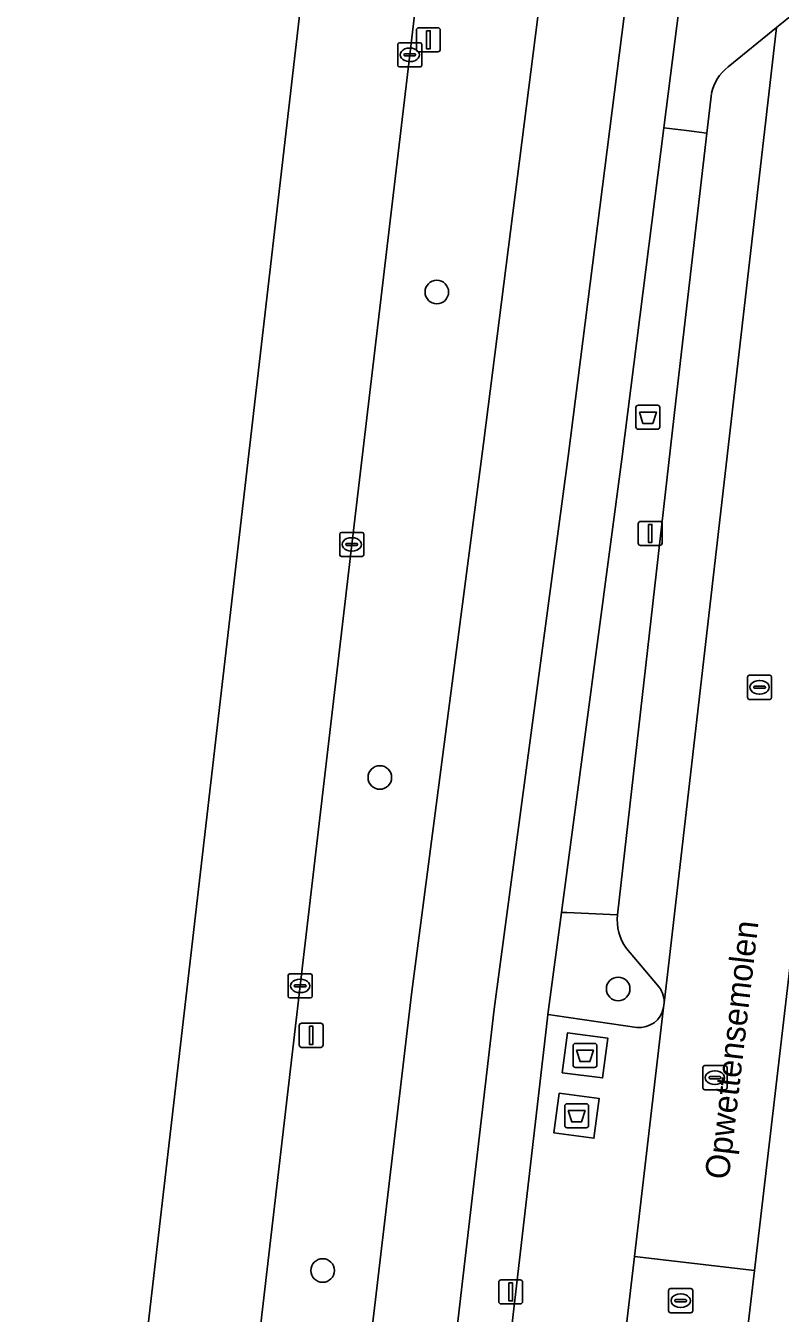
# Model space of a CAD drawing. Extents: x 161241 to 161758, y 384138 to 384885.
# Drawn here: x 161277.3 to 161308.6, y 384518.6 to 384572 of the extents above; entities that cross this region are included whole.
import ezdxf

# ---------------------------------------------------------------- set-up
doc = ezdxf.new("R2010")
doc.units = 0
for name, color, linetype in [('IMGEO_Afval_apart_plaats', 7, 'Continuous'), ('IMGEO_Afvalbak', 7, 'Continuous'), ('IMGEO_Berm_groen', 7, 'Continuous'), ('IMGEO_Boom', 7, 'Continuous'), ('IMGEO_Fietspad_gesloten', 7, 'Continuous'), ('IMGEO_Kolk', 7, 'Continuous'), ('IMGEO_Lichtmast', 7, 'Continuous'), ('IMGEO_Openbare_ruimte_label', 7, 'Continuous'), ('IMGEO_OVBaan_gesloten', 7, 'Continuous'), ('IMGEO_Parkeervlak_open', 7, 'Continuous'), ('IMGEO_Rijbaan_lokaal_open', 7, 'Continuous'), ('IMGEO_Rioolput', 7, 'Continuous'), ('IMGEO_Voetpad_gesloten', 7, 'Continuous'), ('IMGEO_Voetpad_open', 7, 'Continuous')]:
    doc.layers.add(name, color=color, linetype=linetype)

msp = doc.modelspace()

# ---------------------------------------------------------------- linework, layer by layer
at = {"layer": 'IMGEO_Afval_apart_plaats'}
for p, q in [((161300.028, 384528.867), (161300.028, 384529.667)), ((161300.028, 384529.667), (161300.028, 384528.867)), ((161300.128, 384529.767), (161300.918, 384529.767)), ((161300.918, 384529.767), (161300.128, 384529.767)), ((161301.018, 384529.667), (161301.018, 384528.867)), ((161301.018, 384528.867), (161301.018, 384529.667)), ((161300.918, 384528.767), (161300.128, 384528.767)), ((161300.128, 384528.767), (161300.918, 384528.767)), ((161299.68, 384526.363), (161299.68, 384527.163)), ((161299.68, 384527.163), (161299.68, 384526.363)), ((161299.78, 384527.263), (161300.57, 384527.263)), ((161300.57, 384527.263), (161299.78, 384527.263)), ((161300.67, 384527.163), (161300.67, 384526.363)), ((161300.67, 384526.363), (161300.67, 384527.163)), ((161300.57, 384526.263), (161299.78, 384526.263)), ((161299.78, 384526.263), (161300.57, 384526.263))]:
    msp.add_line(p, q, dxfattribs=at)
for points in [[(161300.171, 384529.481), (161300.875, 384529.481), (161300.726, 384529.011), (161300.32, 384529.011), (161300.171, 384529.481)], [(161299.823, 384526.977), (161300.527, 384526.977), (161300.378, 384526.507), (161299.972, 384526.507), (161299.823, 384526.977)]]:
    msp.add_lwpolyline(points, dxfattribs=at)
for centre, start, end in [((161300.128, 384529.667), 90, 180), ((161300.128, 384529.667), 90, 180), ((161300.918, 384529.667), 0, 90), ((161300.918, 384529.667), 360, 90), ((161300.128, 384528.867), 180, 270), ((161300.128, 384528.867), 180, 270), ((161300.918, 384528.867), 270, 0), ((161300.918, 384528.867), 270, 0), ((161299.78, 384527.163), 90, 180), ((161299.78, 384527.163), 90, 180), ((161300.57, 384527.163), 0, 90), ((161300.57, 384527.163), 360, 90), ((161299.78, 384526.363), 180, 270), ((161299.78, 384526.363), 180, 270), ((161300.57, 384526.363), 270, 0), ((161300.57, 384526.363), 270, 0)]:
    msp.add_arc(centre, 0.1, start, end, dxfattribs=at)
at = {"layer": 'IMGEO_Afvalbak'}
for p, q in [((161302.637, 384555.341), (161302.637, 384556.141)), ((161302.637, 384556.141), (161302.637, 384555.341)), ((161302.737, 384556.241), (161303.527, 384556.241)), ((161303.527, 384556.241), (161302.737, 384556.241)), ((161303.627, 384556.141), (161303.627, 384555.341)), ((161303.627, 384555.341), (161303.627, 384556.141)), ((161303.527, 384555.241), (161302.737, 384555.241)), ((161302.737, 384555.241), (161303.527, 384555.241))]:
    msp.add_line(p, q, dxfattribs=at)
msp.add_lwpolyline([(161302.78, 384555.955), (161303.484, 384555.955), (161303.335, 384555.485), (161302.929, 384555.485), (161302.78, 384555.955)], dxfattribs=at)
for centre, start, end in [((161302.737, 384556.141), 90, 180), ((161302.737, 384556.141), 90, 180), ((161303.527, 384556.141), 0, 90), ((161303.527, 384556.141), 360, 90), ((161302.737, 384555.341), 180, 270), ((161302.737, 384555.341), 180, 270), ((161303.527, 384555.341), 270, 0), ((161303.527, 384555.341), 270, 0)]:
    msp.add_arc(centre, 0.1, start, end, dxfattribs=at)
at = {"layer": 'IMGEO_Berm_groen'}
for points in [[(161278.307, 384403.15), (161286.202, 384471.417), (161293.323, 384531.813), (161296.311, 384554.647), (161300.999, 384591.473), (161306.453, 384637.728), (161301.117, 384638.364), (161300.355, 384631.67), (161297.994, 384611.38), (161295.634, 384591.049), (161293.255, 384570.775), (161290.848, 384550.464), (161288.707, 384532.15), (161288.472, 384530.133), (161286.341, 384511.851), (161283.768, 384490.025), (161281.583, 384471.698), (161279.185, 384451.364)], [(161306.46, 384570.27), (161308.464, 384571.907), (161309.261, 384572.542), (161308.413, 384573.592), (161305.263, 384577.494), (161305.062, 384577.742), (161303.794, 384567.742), (161304.73, 384567.63), (161305.574, 384567.529), (161305.764, 384569.177)], [(161301.866, 384535.1), (161299.776, 384535.191), (161299.549, 384535.196), (161298.986, 384530.962), (161299.086, 384530.946), (161299.265, 384530.92), (161302.672, 384530.431)], [(161303.525, 384532.183), (161302.238, 384533.704)], [(161303.783, 384531.252), (161303.807, 384531.45)]]:
    msp.add_lwpolyline(points, dxfattribs=at)
msp.add_lwpolyline([(161305.574, 384567.529), (161304.73, 384567.63), (161303.794, 384567.742), (161302.052, 384554.002), (161299.549, 384535.196), (161299.776, 384535.191), (161301.866, 384535.1), (161304.293, 384556.423)], close=True, dxfattribs=at)
for centre, radius, start, end in [((161307.568, 384568.797), 1.843, 126.9338, 168.0899), ((161304.006, 384534.923), 2.147, 175.2616, 214.5808), ((161302.796, 384531.482), 1.012, 358.2094, 43.8761), ((161302.782, 384531.445), 1.02, 263.834, 349.0929)]:
    msp.add_arc(centre, radius, start, end, dxfattribs=at)
at = {"layer": 'IMGEO_Boom'}
for centre in [(161294.375, 384560.934), (161292.011, 384540.797), (161301.899, 384532.026), (161289.64, 384520.345)]:
    msp.add_circle(centre, 0.489, dxfattribs=at)
at = {"layer": 'IMGEO_Fietspad_gesloten'}
for points in [[(161258.742, 384157.135), (161260.876, 384184.71), (161262.854, 384210.484), (161266.448, 384261.586), (161267.146, 384270.325), (161268.291, 384284.663), (161268.569, 384287.683), (161268.583, 384287.814), (161270.005, 384301.578), (161270.134, 384303.063), (161273.019, 384327.449), (161276.269, 384355.259), (161281.811, 384402.692), (161289.671, 384470.352), (161296.755, 384531.182), (161299.82, 384554.106), (161304.483, 384590.763), (161310.58, 384642.356), (161311.044, 384646.284), (161311.712, 384651.942), (161311.774, 384652.424)], [(161308.263, 384652.525), (161306.453, 384637.728), (161300.999, 384591.473), (161296.311, 384554.647), (161293.323, 384531.813), (161286.202, 384471.417), (161278.307, 384403.15), (161275.866, 384382.258), (161272.845, 384356.399), (161269.542, 384328.133), (161269.524, 384327.978), (161266.559, 384302.554), (161265.412, 384302.67), (161262.065, 384303.024), (161261.777, 384300.445), (161262.272, 384300.399), (161264.329, 384300.231)]]:
    msp.add_lwpolyline(points, dxfattribs=at)
at = {"layer": 'IMGEO_Kolk'}
for p, q in [((161292.829, 384571.275), (161293.681, 384571.275)), ((161292.754, 384570.349), (161292.754, 384571.201)), ((161293.013, 384570.769), (161293.013, 384570.781)), ((161293.451, 384570.732), (161293.053, 384570.732)), ((161293.056, 384570.818), (161293.454, 384570.818)), ((161293.242, 384571.055), (161293.267, 384571.055)), ((161293.497, 384570.781), (161293.497, 384570.769)), ((161293.755, 384571.201), (161293.755, 384570.349)), ((161293.681, 384570.275), (161292.829, 384570.275)), ((161293.265, 384570.495), (161293.24, 384570.495)), ((161290.422, 384550.964), (161291.274, 384550.964)), ((161290.347, 384550.038), (161290.347, 384550.89)), ((161290.606, 384550.458), (161290.606, 384550.47)), ((161291.044, 384550.421), (161290.646, 384550.421)), ((161290.649, 384550.507), (161291.047, 384550.507)), ((161290.835, 384550.744), (161290.86, 384550.744)), ((161291.09, 384550.47), (161291.09, 384550.458)), ((161291.348, 384550.89), (161291.348, 384550.038)), ((161291.274, 384549.964), (161290.422, 384549.964)), ((161290.858, 384550.184), (161290.833, 384550.184)), ((161307.34, 384545.038), (161308.192, 384545.038)), ((161307.265, 384544.112), (161307.265, 384544.964)), ((161307.524, 384544.532), (161307.524, 384544.544)), ((161307.567, 384544.581), (161307.965, 384544.581)), ((161307.753, 384544.818), (161307.778, 384544.818)), ((161308.008, 384544.544), (161308.008, 384544.532)), ((161308.266, 384544.964), (161308.266, 384544.112)), ((161308.192, 384544.038), (161307.34, 384544.038)), ((161307.962, 384544.495), (161307.564, 384544.495)), ((161307.776, 384544.258), (161307.751, 384544.258)), ((161288.206, 384531.724), (161288.206, 384532.576)), ((161288.281, 384532.65), (161289.133, 384532.65)), ((161288.694, 384532.43), (161288.719, 384532.43)), ((161289.207, 384532.576), (161289.207, 384531.724)), ((161288.465, 384532.144), (161288.465, 384532.156)), ((161288.903, 384532.107), (161288.505, 384532.107)), ((161288.508, 384532.193), (161288.906, 384532.193)), ((161288.717, 384531.87), (161288.692, 384531.87)), ((161288.949, 384532.156), (161288.949, 384532.144)), ((161289.133, 384531.65), (161288.281, 384531.65)), ((161305.413, 384527.916), (161305.413, 384528.768)), ((161305.488, 384528.842), (161306.34, 384528.842)), ((161305.901, 384528.622), (161305.926, 384528.622)), ((161306.414, 384528.768), (161306.414, 384527.916)), ((161305.672, 384528.336), (161305.672, 384528.348)), ((161306.11, 384528.299), (161305.712, 384528.299)), ((161305.715, 384528.385), (161306.113, 384528.385)), ((161305.924, 384528.062), (161305.899, 384528.062)), ((161306.156, 384528.348), (161306.156, 384528.336)), ((161306.34, 384527.842), (161305.488, 384527.842))]:
    msp.add_line(p, q, dxfattribs=at)
for points in [[(161292.829, 384571.275), (161293.681, 384571.275)], [(161292.754, 384570.349), (161292.754, 384571.201)], [(161293.755, 384571.201), (161293.755, 384570.349)], [(161293.681, 384570.275), (161292.829, 384570.275)], [(161290.422, 384550.964), (161291.274, 384550.964)], [(161290.347, 384550.038), (161290.347, 384550.89)], [(161291.348, 384550.89), (161291.348, 384550.038)], [(161291.274, 384549.964), (161290.422, 384549.964)], [(161307.34, 384545.038), (161308.192, 384545.038)], [(161307.265, 384544.112), (161307.265, 384544.964)], [(161308.266, 384544.964), (161308.266, 384544.112)], [(161308.192, 384544.038), (161307.34, 384544.038)], [(161288.206, 384531.724), (161288.206, 384532.576)], [(161288.281, 384532.65), (161289.133, 384532.65)], [(161289.207, 384532.576), (161289.207, 384531.724)], [(161289.133, 384531.65), (161288.281, 384531.65)], [(161305.413, 384527.916), (161305.413, 384528.768)], [(161305.488, 384528.842), (161306.34, 384528.842)], [(161306.414, 384528.768), (161306.414, 384527.916)], [(161306.34, 384527.842), (161305.488, 384527.842)]]:
    msp.add_lwpolyline(points, dxfattribs=at)
for centre, radius, start, end in [((161292.831, 384571.199), 0.0765, 91.552, 178.448), ((161292.831, 384571.199), 0.0765, 91.552, 178.448), ((161293.679, 384571.199), 0.0765, 1.552, 88.448), ((161293.679, 384571.199), 0.0765, 1.552, 88.448), ((161293.053, 384570.778), 0.0403, 85.8775, 175.7526), ((161293.05, 384570.768), 0.0366, 178.938, 274.7102), ((161293.454, 384570.775), 0.043, 264.8664, 352.4533), ((161293.458, 384570.78), 0.0386, 1.7309, 96.639), ((161292.831, 384570.351), 0.0765, 181.552, 268.448), ((161292.831, 384570.351), 0.0765, 181.552, 268.448), ((161293.679, 384570.351), 0.0765, 271.552, 358.448), ((161293.679, 384570.351), 0.0765, 271.552, 358.448), ((161290.424, 384550.888), 0.0765, 91.552, 178.448), ((161290.424, 384550.888), 0.0765, 91.552, 178.448), ((161291.272, 384550.888), 0.0765, 1.552, 88.448), ((161291.272, 384550.888), 0.0765, 1.552, 88.448), ((161290.646, 384550.467), 0.0403, 85.8775, 175.7526), ((161290.643, 384550.457), 0.0366, 178.938, 274.7102), ((161291.047, 384550.464), 0.043, 264.8664, 352.4533), ((161291.051, 384550.469), 0.0386, 1.7309, 96.639), ((161290.424, 384550.04), 0.0765, 181.552, 268.448), ((161290.424, 384550.04), 0.0765, 181.552, 268.448), ((161291.272, 384550.04), 0.0765, 271.552, 358.448), ((161291.272, 384550.04), 0.0765, 271.552, 358.448), ((161307.342, 384544.962), 0.0765, 91.552, 178.448), ((161307.342, 384544.962), 0.0765, 91.552, 178.448), ((161308.19, 384544.962), 0.0765, 1.552, 88.448), ((161308.19, 384544.962), 0.0765, 1.552, 88.448), ((161307.564, 384544.541), 0.0403, 85.8775, 175.7526), ((161307.561, 384544.531), 0.0366, 178.938, 274.7102), ((161307.965, 384544.538), 0.043, 264.8664, 352.4533), ((161307.969, 384544.543), 0.0386, 1.7309, 96.639), ((161307.342, 384544.114), 0.0765, 181.552, 268.448), ((161307.342, 384544.114), 0.0765, 181.552, 268.448), ((161308.19, 384544.114), 0.0765, 271.552, 358.448), ((161308.19, 384544.114), 0.0765, 271.552, 358.448), ((161288.283, 384532.574), 0.0765, 91.552, 178.448), ((161288.283, 384532.574), 0.0765, 91.552, 178.448), ((161289.131, 384532.574), 0.0765, 1.552, 88.448), ((161289.131, 384532.574), 0.0765, 1.552, 88.448), ((161288.283, 384531.726), 0.0765, 181.552, 268.448), ((161288.283, 384531.726), 0.0765, 181.552, 268.448), ((161288.505, 384532.153), 0.0403, 85.8775, 175.7526), ((161288.502, 384532.143), 0.0366, 178.938, 274.7102), ((161288.906, 384532.15), 0.043, 264.8664, 352.4533), ((161288.91, 384532.155), 0.0386, 1.7309, 96.639), ((161289.131, 384531.726), 0.0765, 271.552, 358.448), ((161289.131, 384531.726), 0.0765, 271.552, 358.448), ((161305.49, 384528.766), 0.0765, 91.552, 178.448), ((161305.49, 384528.766), 0.0765, 91.552, 178.448), ((161306.338, 384528.766), 0.0765, 1.552, 88.448), ((161306.338, 384528.766), 0.0765, 1.552, 88.448), ((161305.712, 384528.345), 0.0403, 85.8775, 175.7526), ((161305.709, 384528.335), 0.0366, 178.938, 274.7102), ((161306.113, 384528.342), 0.043, 264.8664, 352.4533), ((161306.117, 384528.347), 0.0386, 1.7309, 96.639), ((161305.49, 384527.918), 0.0765, 181.552, 268.448), ((161305.49, 384527.918), 0.0765, 181.552, 268.448), ((161306.338, 384527.918), 0.0765, 271.552, 358.448), ((161306.338, 384527.918), 0.0765, 271.552, 358.448)]:
    msp.add_arc(centre, radius, start, end, dxfattribs=at)
for centre, major_axis, ratio, start_param, end_param in [((161293.241, 384570.775), (-0.387, 0.002), 0.722429, 4.712389, 7.853982), ((161293.266, 384570.775), (-0.39, 0.002), 0.717154, 1.570796, 4.712389), ((161290.834, 384550.464), (-0.387, 0.002), 0.722429, 4.712389, 7.853982), ((161290.859, 384550.464), (-0.39, 0.002), 0.717154, 1.570796, 4.712389), ((161307.752, 384544.538), (-0.387, 0.002), 0.722429, 4.712389, 7.853982), ((161307.777, 384544.538), (-0.39, 0.002), 0.717154, 1.570796, 4.712389), ((161288.693, 384532.15), (-0.387, 0.002), 0.722429, 4.712389, 7.853982), ((161288.718, 384532.15), (-0.39, 0.002), 0.717154, 1.570796, 4.712389), ((161305.9, 384528.342), (-0.387, 0.002), 0.722429, 4.712389, 7.853982), ((161305.925, 384528.342), (-0.39, 0.002), 0.717154, 1.570796, 4.712389)]:
    msp.add_ellipse(centre, major_axis=major_axis, ratio=ratio, start_param=start_param, end_param=end_param, dxfattribs=at)
at = {"layer": 'IMGEO_Lichtmast'}
for p, q in [((161293.53, 384571.001), (161293.53, 384571.801)), ((161293.53, 384571.801), (161293.53, 384571.001)), ((161293.63, 384571.901), (161294.42, 384571.901)), ((161294.42, 384571.901), (161293.63, 384571.901)), ((161294.52, 384571.801), (161294.52, 384571.001)), ((161294.52, 384571.001), (161294.52, 384571.801)), ((161294.42, 384570.901), (161293.63, 384570.901)), ((161293.63, 384570.901), (161294.42, 384570.901)), ((161302.731, 384550.52), (161302.731, 384551.32)), ((161302.731, 384551.32), (161302.731, 384550.52)), ((161302.831, 384551.42), (161303.621, 384551.42)), ((161303.621, 384551.42), (161302.831, 384551.42)), ((161303.721, 384551.32), (161303.721, 384550.52)), ((161303.721, 384550.52), (161303.721, 384551.32)), ((161303.621, 384550.42), (161302.831, 384550.42)), ((161302.831, 384550.42), (161303.621, 384550.42)), ((161288.669, 384529.701), (161288.669, 384530.501)), ((161288.669, 384530.501), (161288.669, 384529.701)), ((161288.769, 384530.601), (161289.559, 384530.601)), ((161289.559, 384530.601), (161288.769, 384530.601)), ((161289.659, 384530.501), (161289.659, 384529.701)), ((161289.659, 384529.701), (161289.659, 384530.501)), ((161289.559, 384529.601), (161288.769, 384529.601)), ((161288.769, 384529.601), (161289.559, 384529.601)), ((161297.046, 384519.957), (161297.836, 384519.957)), ((161297.836, 384519.957), (161297.046, 384519.957)), ((161296.946, 384519.057), (161296.946, 384519.857)), ((161296.946, 384519.857), (161296.946, 384519.057)), ((161297.936, 384519.857), (161297.936, 384519.057)), ((161297.936, 384519.057), (161297.936, 384519.857)), ((161297.836, 384518.957), (161297.046, 384518.957)), ((161297.046, 384518.957), (161297.836, 384518.957))]:
    msp.add_line(p, q, dxfattribs=at)
for points in [[(161293.95, 384571.776), (161294.1, 384571.776), (161294.1, 384571.026), (161293.95, 384571.026), (161293.95, 384571.776)], [(161303.151, 384551.295), (161303.301, 384551.295), (161303.301, 384550.545), (161303.151, 384550.545), (161303.151, 384551.295)], [(161289.089, 384530.476), (161289.239, 384530.476), (161289.239, 384529.726), (161289.089, 384529.726), (161289.089, 384530.476)], [(161297.366, 384519.832), (161297.516, 384519.832), (161297.516, 384519.082), (161297.366, 384519.082), (161297.366, 384519.832)]]:
    msp.add_lwpolyline(points, dxfattribs=at)
for centre, start, end in [((161293.63, 384571.801), 90, 180), ((161293.63, 384571.801), 90, 180), ((161294.42, 384571.801), 0, 90), ((161294.42, 384571.801), 360, 90), ((161293.63, 384571.001), 180, 270), ((161293.63, 384571.001), 180, 270), ((161294.42, 384571.001), 270, 0), ((161294.42, 384571.001), 270, 0), ((161302.831, 384551.32), 90, 180), ((161302.831, 384551.32), 90, 180), ((161303.621, 384551.32), 0, 90), ((161303.621, 384551.32), 360, 90), ((161302.831, 384550.52), 180, 270), ((161302.831, 384550.52), 180, 270), ((161303.621, 384550.52), 270, 0), ((161303.621, 384550.52), 270, 0), ((161288.769, 384530.501), 90, 180), ((161288.769, 384530.501), 90, 180), ((161289.559, 384530.501), 0, 90), ((161289.559, 384530.501), 360, 90), ((161288.769, 384529.701), 180, 270), ((161288.769, 384529.701), 180, 270), ((161289.559, 384529.701), 270, 0), ((161289.559, 384529.701), 270, 0), ((161297.046, 384519.857), 90, 180), ((161297.046, 384519.857), 90, 180), ((161297.836, 384519.857), 0, 90), ((161297.836, 384519.857), 360, 90), ((161297.046, 384519.057), 180, 270), ((161297.046, 384519.057), 180, 270), ((161297.836, 384519.057), 270, 0), ((161297.836, 384519.057), 270, 0)]:
    msp.add_arc(centre, 0.1, start, end, dxfattribs=at)
at = {"layer": 'IMGEO_OVBaan_gesloten'}
for points in [[(161312.353, 384812.006), (161309.921, 384834.117), (161309.774, 384835.487), (161309.446, 384838.541), (161309.033, 384842.394), (161308.618, 384846.264), (161308.42, 384848.049), (161305.427, 384848.093), (161310.221, 384805.365), (161309.046, 384772.256), (161307.924, 384740.658), (161299.466, 384666.717), (161288.788, 384573.374), (161256.675, 384295.749), (161254.709, 384278.75), (161244.663, 384173.474), (161243.814, 384162.675), (161243.598, 384159.911), (161243.455, 384158.862), (161242.942, 384154.711), (161242.923, 384154.593), (161242.753, 384153.458), (161241.269, 384137.91)], [(161261.738, 384300.096), (161261.777, 384300.445), (161262.065, 384303.024), (161262.902, 384310.522), (161264.916, 384328.431), (161267.197, 384347.869), (161269.457, 384367.164), (161271.789, 384387.356), (161274.112, 384407.478), (161276.721, 384430.069), (161279.185, 384451.364), (161281.583, 384471.698), (161283.768, 384490.025), (161286.341, 384511.851), (161288.472, 384530.133), (161288.707, 384532.15), (161290.848, 384550.464), (161293.255, 384570.775), (161295.634, 384591.049), (161297.994, 384611.38), (161300.355, 384631.67), (161301.117, 384638.364), (161302.766, 384651.987), (161302.856, 384653.145)]]:
    msp.add_lwpolyline(points, dxfattribs=at)
at = {"layer": 'IMGEO_Parkeervlak_open'}
for points in [[(161303.807, 384531.45), (161303.973, 384532.865), (161308.464, 384571.907), (161306.46, 384570.27)], [(161305.764, 384569.177), (161305.574, 384567.529), (161304.293, 384556.423), (161301.866, 384535.1)], [(161302.238, 384533.704), (161303.525, 384532.183)], [(161300.111, 384500), (161302.017, 384516.22), (161302.57, 384520.925), (161303.783, 384531.252)], [(161302.672, 384530.431), (161299.265, 384530.92), (161299.086, 384530.946), (161298.986, 384530.962), (161298.968, 384530.827), (161291.483, 384466.168), (161291.644, 384466.15), (161295.04, 384465.761), (161296.054, 384465.353), (161299.421, 384494.132), (161300.111, 384500)]]:
    msp.add_lwpolyline(points, dxfattribs=at)
for points in [[(161299.582, 384528.546), (161299.793, 384530.202), (161301.465, 384529.988), (161301.254, 384528.333)], [(161299.236, 384526.051), (161299.458, 384527.698), (161301.113, 384527.474), (161300.891, 384525.828)]]:
    msp.add_lwpolyline(points, close=True, dxfattribs=at)
for centre, radius, start, end in [((161307.568, 384568.797), 1.843, 126.9338, 168.0899), ((161304.006, 384534.923), 2.147, 175.2616, 214.5808), ((161302.796, 384531.482), 1.012, 358.2094, 43.8761), ((161302.782, 384531.445), 1.02, 263.834, 349.0929)]:
    msp.add_arc(centre, radius, start, end, dxfattribs=at)
at = {"layer": 'IMGEO_Rijbaan_lokaal_open'}
msp.add_lwpolyline([(161313.874, 384576.41), (161312.882, 384575.302), (161311.629, 384574.432), (161309.261, 384572.542), (161308.464, 384571.907), (161303.973, 384532.865), (161303.807, 384531.45), (161303.783, 384531.252), (161302.57, 384520.925), (161307.548, 384520.344), (161309.149, 384533.964), (161313.194, 384569.245), (161319.366, 384573.967), (161321.313, 384590.613), (161323.425, 384609.052), (161324.303, 384616.759)], dxfattribs=at)
msp.add_lwpolyline([(161307.548, 384520.344), (161302.57, 384520.925), (161302.017, 384516.22), (161306.995, 384515.642)], close=True, dxfattribs=at)
at = {"layer": 'IMGEO_Rioolput'}
for p, q in [((161303.993, 384518.666), (161303.993, 384519.518)), ((161304.068, 384519.592), (161304.92, 384519.592)), ((161304.994, 384519.518), (161304.994, 384518.666)), ((161304.252, 384519.086), (161304.252, 384519.098)), ((161304.69, 384519.049), (161304.292, 384519.049)), ((161304.295, 384519.135), (161304.693, 384519.135)), ((161304.481, 384519.372), (161304.506, 384519.372)), ((161304.736, 384519.098), (161304.736, 384519.086)), ((161304.92, 384518.592), (161304.068, 384518.592)), ((161304.504, 384518.812), (161304.479, 384518.812))]:
    msp.add_line(p, q, dxfattribs=at)
for points in [[(161303.993, 384518.666), (161303.993, 384519.518)], [(161304.068, 384519.592), (161304.92, 384519.592)], [(161304.994, 384519.518), (161304.994, 384518.666)], [(161304.92, 384518.592), (161304.068, 384518.592)]]:
    msp.add_lwpolyline(points, dxfattribs=at)
for centre, radius, start, end in [((161304.07, 384519.516), 0.0765, 91.552, 178.448), ((161304.07, 384519.516), 0.0765, 91.552, 178.448), ((161304.918, 384519.516), 0.0765, 1.552, 88.448), ((161304.918, 384519.516), 0.0765, 1.552, 88.448), ((161304.292, 384519.095), 0.0403, 85.8775, 175.7526), ((161304.289, 384519.085), 0.0366, 178.938, 274.7102), ((161304.693, 384519.092), 0.043, 264.8664, 352.4533), ((161304.697, 384519.097), 0.0386, 1.7309, 96.639), ((161304.07, 384518.668), 0.0765, 181.552, 268.448), ((161304.07, 384518.668), 0.0765, 181.552, 268.448), ((161304.918, 384518.668), 0.0765, 271.552, 358.448), ((161304.918, 384518.668), 0.0765, 271.552, 358.448)]:
    msp.add_arc(centre, radius, start, end, dxfattribs=at)
for centre, major_axis, ratio, start_param, end_param in [((161304.48, 384519.092), (-0.387, 0.002), 0.722429, 4.712389, 7.853982), ((161304.505, 384519.092), (-0.39, 0.002), 0.717154, 1.570796, 4.712389)]:
    msp.add_ellipse(centre, major_axis=major_axis, ratio=ratio, start_param=start_param, end_param=end_param, dxfattribs=at)
at = {"layer": 'IMGEO_Voetpad_gesloten'}
for points in [[(161301.465, 384529.988), (161299.793, 384530.202), (161299.582, 384528.546), (161301.254, 384528.333)], [(161301.113, 384527.474), (161299.458, 384527.698), (161299.236, 384526.051), (161300.891, 384525.828)]]:
    msp.add_lwpolyline(points, close=True, dxfattribs=at)
at = {"layer": 'IMGEO_Voetpad_open'}
for points in [[(161311.774, 384652.424), (161311.712, 384651.942), (161311.044, 384646.284), (161310.58, 384642.356), (161304.483, 384590.763), (161299.82, 384554.106), (161296.755, 384531.182), (161289.671, 384470.352), (161281.811, 384402.692), (161276.269, 384355.259), (161273.019, 384327.449), (161270.134, 384303.063), (161270.005, 384301.578)], [(161366.853, 384643.333), (161336.314, 384646.823), (161333.288, 384644.347), (161331.082, 384642.543), (161326.899, 384639.121), (161324.303, 384616.759), (161323.425, 384609.052), (161321.313, 384590.613), (161319.366, 384573.967), (161313.194, 384569.245), (161309.149, 384533.964), (161307.548, 384520.344), (161306.995, 384515.642), (161305.156, 384500), (161304.927, 384498.052), (161301.344, 384467.341), (161306.178, 384461.35), (161304.65, 384447.935)], [(161289.844, 384452.553), (161298.017, 384459.712), (161296.049, 384461.925), (161290.446, 384457.047), (161291.483, 384466.168), (161298.968, 384530.827), (161298.986, 384530.962), (161299.549, 384535.196), (161302.052, 384554.002), (161303.794, 384567.742), (161305.062, 384577.742)]]:
    msp.add_lwpolyline(points, dxfattribs=at)

# ---------------------------------------------------------------- texts
at = {"layer": 'IMGEO_Openbare_ruimte_label'}
msp.add_text('Opwettensemolen', height=1, rotation=83.394, dxfattribs=at).set_placement((161306.483, 384524.09))

doc.saveas('drawing.dxf')
